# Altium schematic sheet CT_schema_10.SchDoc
size 146 x 119 mm
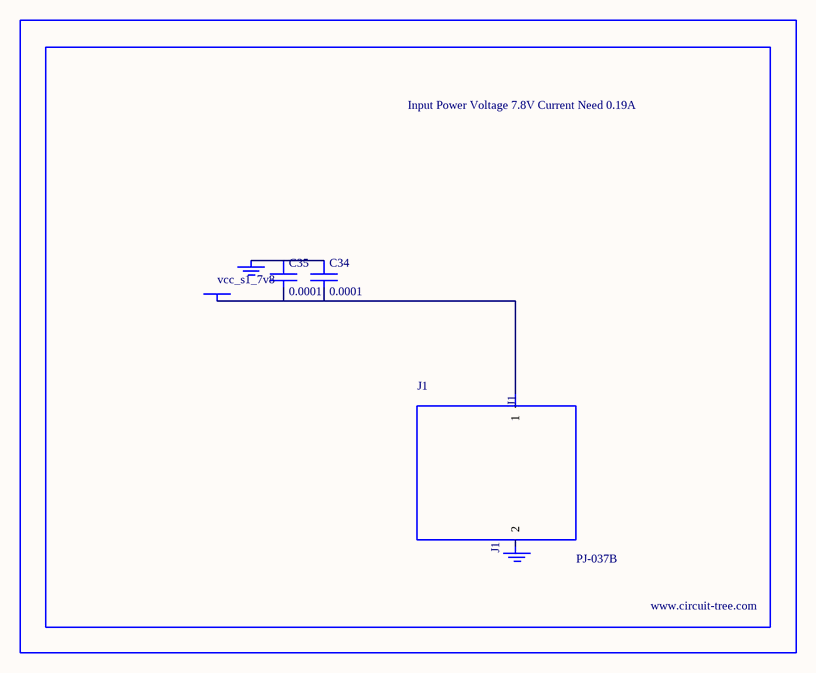
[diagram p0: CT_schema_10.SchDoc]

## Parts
BORDER9  (no value)
C34  0.0001  [EXV-9H]
C35  0.0001  [EXV-9H]
GND_INSTANCE_9_0  (no value)
GND_INSTANCE_9_1  (no value)
J1  PJ-037B  [PJ-037B_PACKAGE]
POWER_INSTANCE_9_0  vcc_s1_7v8

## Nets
NetC34_1: C34.1 C35.1 GND_INSTANCE_9_0.0(GND)
NetC34_2: C34.2 C35.2 J1.1 POWER_INSTANCE_9_0.0(PWR)

Not connected (* = marked no-connect by the designer): GND_INSTANCE_9_1 0(GND); J1 2

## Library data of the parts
BORDER9 = BORDER_PAGE9
C34 C35 = EDK107M035A9HAA
GND_INSTANCE_9_0 GND_INSTANCE_9_1 = GND
POWER_INSTANCE_9_0 = PWR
